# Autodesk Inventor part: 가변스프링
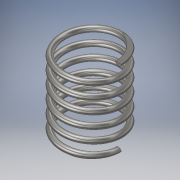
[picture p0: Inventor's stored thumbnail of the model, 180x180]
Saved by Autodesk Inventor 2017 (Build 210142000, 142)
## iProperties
Part Number: 가변스프링
Material: 스테인레스 스틸
Document SubType Name: Modeling
Designer: 00-00
Density: 8 g/cm^3
Appearance: 반연마
Mass: 9.32026 g
Surface Area: 23.6146 cm^2
Volume: 1.16503 cm^3
Author: 00-00
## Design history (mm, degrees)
sketch "스케치1"
  geometry: L1 (0, 0)-(10, 0); L2 (10, 0)-(10, 26.7); L3 (10, 26.7)-(0, 26.7); L4 (0, 26.7)-(0, 0); C1 r 1 at (10, 0)
  constraints: 8 end point, 2 parallel, 1 centre point, 1 coincident, 1 horizontal, 1 perpendicular
  dimensions: "d0" = 20 diameter of L2 L4; "d1" = 2 diameter of C1; "d2" = 26.7 distance of L3.end L1.start (derived)
feature "코일1" sketch "스케치1" pitch "d3" = 26.7 (= d2); turns "d5" = 6; dims "d4" = 26.7 (= d2), "d6" = 0, angle "d7" = 90 deg, angle "d8" = 90 deg, "d9" = 0, "d10" = 0
node "작업 평면1"
sketch "스케치2"
  geometry: L1 (9, 0)-(11, 0) reference; 1 further point
  constraints: 1 horizontal alignment
extrude "돌출1" cut sketch "스케치2" stored distance "d12" = 10; taper "d13" = 0 deg
node "작업 평면3"
sketch "스케치3"
  geometry: L1 (-1, 0)-(1, 0) reference; 1 further point
  constraints: 1 horizontal alignment
extrude "돌출2" cut sketch "스케치3" stored distance "d15" = 10; taper "d16" = 0 deg
node "솔리드1"
node "절단 모서리 투영1"
node "절단 모서리 투영2"
other parameters: "d11" = 90 deg
